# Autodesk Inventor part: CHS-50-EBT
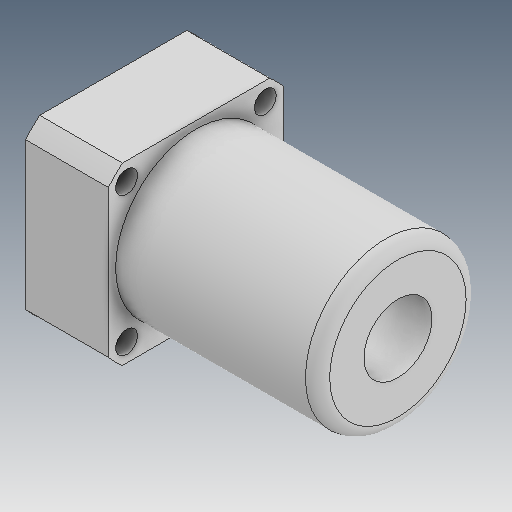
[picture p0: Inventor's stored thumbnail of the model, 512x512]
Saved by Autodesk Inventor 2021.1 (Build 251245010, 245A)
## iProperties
Created: 2019-04
Part Number: CHS-50-EBT
Material: Ogólny
Document SubType Name: Modeling
Designer: user
Density: 1 g/cm^3
Appearance: Domyślna
Author: user
Revision Number: ÈÎºÎ
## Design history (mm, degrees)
feature "ÊäÈë1"
node "Bryła1"
